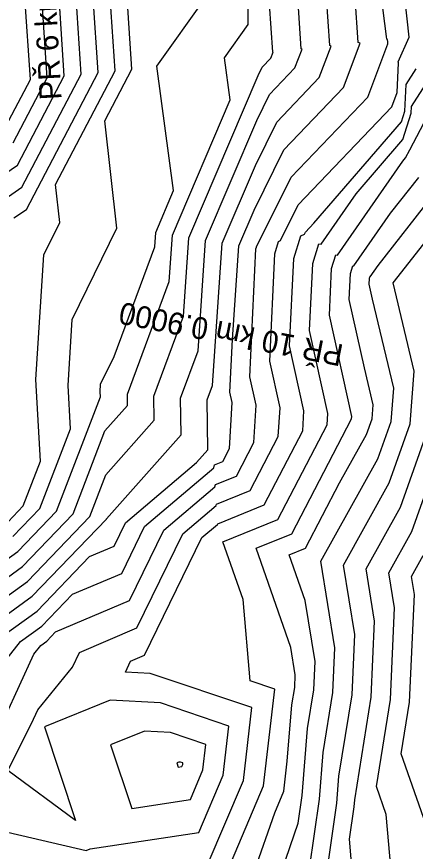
# Model space of a CAD drawing. Extents: x -549394 to -546608, y -1037055 to -1033629.
# Drawn here: x -547088.8 to -546924.3, y -1036607.7 to -1036262.8 of the extents above; entities that cross this region are included whole.
import ezdxf

# ---------------------------------------------------------------- set-up
doc = ezdxf.new("R2010")
doc.units = 0
for name, color, linetype in [('hlavni_vrst', 7, 'Continuous'), ('norm_vrst', 7, 'Continuous'), ('x_popis_pricne_rezy_C31', 7, 'Continuous')]:
    doc.layers.add(name, color=color, linetype=linetype)

msp = doc.modelspace()

# ---------------------------------------------------------------- linework, layer by layer
at = {"layer": 'hlavni_vrst'}
for p, q in [((-547069.17, -1036287.31), (-547074.04, -1036213.03)), ((-546947.86, -1036273.47), (-546950.44, -1036236.45)), ((-547030.9, -1036283.3), (-547001.91, -1036242.41)), ((-546953.97, -1036292.02), (-546947.07, -1036273.75)), ((-546947.07, -1036273.75), (-546947.86, -1036273.47)), ((-547024.04, -1036334.63), (-547030.9, -1036283.3)), ((-547088.4, -1036324.11), (-547069.17, -1036287.31)), ((-546978.56, -1036317.77), (-546953.97, -1036292.02)), ((-546926.63, -1036317.77), (-546914.41, -1036294.48)), ((-546990.87, -1036342.79), (-546978.56, -1036317.77)), ((-546928.35, -1036321.11), (-546926.63, -1036317.77)), ((-546956.43, -1036361.31), (-546929.51, -1036322.58)), ((-546929.51, -1036322.58), (-546928.35, -1036321.11)), ((-547116.55, -1036343.3), (-547088.4, -1036324.11)), ((-547031.42, -1036351.98), (-547024.04, -1036334.63)), ((-546997.11, -1036357.45), (-546990.87, -1036342.79)), ((-547031.83, -1036357.93), (-547031.42, -1036351.98)), ((-547048.58, -1036403.23), (-547031.83, -1036357.93)), ((-546999.77, -1036396.25), (-546997.11, -1036357.45)), ((-546958.86, -1036366.9), (-546957.09, -1036361.22)), ((-546957.09, -1036361.22), (-546956.43, -1036361.31)), ((-546959.77, -1036386.1), (-546958.86, -1036366.9)), ((-546950.54, -1036427.95), (-546959.77, -1036386.1)), ((-547000.8, -1036417.94), (-546999.77, -1036396.25)), ((-547054.16, -1036414.71), (-547048.58, -1036403.23)), ((-547054.36, -1036417.84), (-547054.16, -1036414.71)), ((-547072.34, -1036467.12), (-547054.25, -1036419.9)), ((-547054.25, -1036419.9), (-547054.36, -1036417.84)), ((-546999.87, -1036422.16), (-547000.8, -1036417.94)), ((-547001, -1036441.26), (-546999.87, -1036422.16)), ((-546975.3, -1036476.49), (-546950.6, -1036428.96)), ((-546950.6, -1036428.96), (-546950.54, -1036427.95)), ((-546925.75, -1036475.49), (-546910.78, -1036433.05)), ((-547003.8, -1036446.65), (-547001, -1036441.26)), ((-547007.17, -1036448.02), (-547003.8, -1036446.65)), ((-547036, -1036473.47), (-547007.5, -1036449.22)), ((-547007.5, -1036449.22), (-547007.17, -1036448.02)), ((-547088.34, -1036483.8), (-547072.34, -1036467.12)), ((-547045.45, -1036492.84), (-547036, -1036473.47)), ((-546990.03, -1036482.48), (-546975.3, -1036476.49)), ((-546935.28, -1036492.56), (-546925.75, -1036475.49)), ((-547115.54, -1036503.49), (-547088.34, -1036483.8)), ((-546975.7, -1036523.47), (-546990.03, -1036482.48)), ((-546932.91, -1036507.04), (-546935.28, -1036492.56)), ((-547065.71, -1036501.45), (-547045.45, -1036492.84)), ((-547078.36, -1036514.64), (-547065.71, -1036501.45)), ((-546934.61, -1036544.99), (-546932.91, -1036507.04)), ((-547087.14, -1036521), (-547078.36, -1036514.64)), ((-547097.18, -1036533.65), (-547087.14, -1036521)), ((-546973.86, -1036534.72), (-546975.7, -1036523.47)), ((-546974.09, -1036540.01), (-546973.86, -1036534.72)), ((-546975.24, -1036547.16), (-546974.09, -1036540.01)), ((-546977.14, -1036570.47), (-546975.24, -1036547.16)), ((-546940.39, -1036580.9), (-546934.61, -1036544.99)), ((-547021.85, -1036570.78), (-547022.77, -1036571.15)), ((-547022.77, -1036571.15), (-547022.2, -1036572.86)), ((-547021.15, -1036570.81), (-547021.85, -1036570.78)), ((-547020.2, -1036571.14), (-547021.15, -1036570.81)), ((-547020.62, -1036572.62), (-547020.28, -1036571.82)), ((-547020.28, -1036571.82), (-547020.2, -1036571.14)), ((-546978.57, -1036582.85), (-546977.14, -1036570.47)), ((-547022.2, -1036572.86), (-547020.62, -1036572.62)), ((-546936.34, -1036592.46), (-546940.39, -1036580.9)), ((-546982.33, -1036591.7), (-546978.57, -1036582.85)), ((-546994.44, -1036626.7), (-546982.33, -1036591.7)), ((-546934.27, -1036616.63), (-546936.34, -1036592.46))]:
    msp.add_line(p, q, dxfattribs=at)
at = {"layer": 'norm_vrst'}
for p, q in [((-547055.19, -1036285.88), (-547062.02, -1036181.85)), ((-546993.29, -1036266.03), (-546992.9, -1036187.88)), ((-547062.18, -1036286.6), (-547068.37, -1036192.34)), ((-546936.18, -1036271.07), (-546946.39, -1036192.56)), ((-546959.62, -1036274.79), (-546964.71, -1036201.82)), ((-546971.37, -1036276.11), (-546975.56, -1036216.01)), ((-547048.21, -1036285.17), (-547052.63, -1036217.76)), ((-547076.15, -1036288.03), (-547079.72, -1036233.71)), ((-546926.84, -1036271.25), (-546929.11, -1036250.4)), ((-547083.14, -1036288.74), (-547085.4, -1036254.39)), ((-547041.22, -1036284.45), (-547043.24, -1036253.68)), ((-546983.13, -1036277.42), (-546984.51, -1036257.66)), ((-547003.08, -1036279.84), (-546993.29, -1036266.03)), ((-546936.1, -1036272.15), (-546936.18, -1036271.07)), ((-546931.41, -1036281.41), (-546926.84, -1036271.25)), ((-546963.97, -1036288.02), (-546959.05, -1036274.99)), ((-546959.05, -1036274.99), (-546959.62, -1036274.79)), ((-546943.96, -1036296.01), (-546935.65, -1036274.01)), ((-546935.8, -1036272.26), (-546936.1, -1036272.15)), ((-546935.62, -1036273.21), (-546935.8, -1036272.26)), ((-546935.65, -1036274.01), (-546935.62, -1036273.21)), ((-546983.99, -1036280.03), (-546983.02, -1036277.46)), ((-546983.02, -1036277.46), (-546983.13, -1036277.42)), ((-546973.98, -1036284.02), (-546971.03, -1036276.23)), ((-546971.03, -1036276.23), (-546971.37, -1036276.11)), ((-547000.76, -1036297.17), (-547003.08, -1036279.84)), ((-546987.44, -1036283.64), (-546983.99, -1036280.03)), ((-546931.75, -1036294.19), (-546931.32, -1036281.88)), ((-546931.32, -1036281.88), (-546931.41, -1036281.41)), ((-546925.95, -1036300), (-546913.32, -1036280.25)), ((-547072.77, -1036332.15), (-547048.21, -1036285.17)), ((-547052.43, -1036305.9), (-547041.22, -1036284.45)), ((-546989.17, -1036287.16), (-546987.44, -1036283.64)), ((-546984.48, -1036295.02), (-546973.98, -1036284.02)), ((-546928.07, -1036290.8), (-546923.97, -1036284.4)), ((-547092.04, -1036305.75), (-547083.14, -1036288.74)), ((-547090.22, -1036314.93), (-547076.15, -1036288.03)), ((-547086.58, -1036333.28), (-547062.18, -1036286.6)), ((-547084.77, -1036342.46), (-547055.19, -1036285.88)), ((-547017.7, -1036354.17), (-546989.17, -1036287.16)), ((-546981.52, -1036306.39), (-546963.97, -1036288.02)), ((-546928.69, -1036301.91), (-546928.07, -1036290.8)), ((-546989.74, -1036305.7), (-546984.48, -1036295.02)), ((-546975.61, -1036329.14), (-546943.96, -1036296.01)), ((-546933.95, -1036300.01), (-546931.75, -1036294.19)), ((-547024.56, -1036353.08), (-547000.76, -1036297.17)), ((-546972.65, -1036340.51), (-546933.95, -1036300.01)), ((-546930, -1036306.2), (-546928.69, -1036301.91)), ((-546929.44, -1036313.62), (-546926.09, -1036302.63)), ((-546926.09, -1036302.63), (-546925.95, -1036300)), ((-547047.46, -1036350.21), (-547052.43, -1036305.9)), ((-547010.84, -1036355.26), (-546989.74, -1036305.7)), ((-546966.15, -1036348.19), (-546930, -1036306.2)), ((-546990.3, -1036324.25), (-546981.52, -1036306.39)), ((-546948.68, -1036335.95), (-546929.44, -1036313.62)), ((-547003.98, -1036356.36), (-546990.3, -1036324.25)), ((-546989.78, -1036357.95), (-546975.61, -1036329.14)), ((-546934.57, -1036344.07), (-546922.91, -1036329.21)), ((-547103.24, -1036344.64), (-547086.58, -1036333.28)), ((-547071, -1036347.87), (-547072.77, -1036332.15)), ((-546963.17, -1036356.8), (-546948.68, -1036335.95)), ((-546939.64, -1036365.56), (-546917.47, -1036337.31)), ((-546979.94, -1036355.34), (-546972.65, -1036340.51)), ((-547089.94, -1036345.99), (-547084.77, -1036342.46)), ((-546949.69, -1036365.81), (-546934.57, -1036344.07)), ((-546933.49, -1036372.76), (-546912.03, -1036345.41)), ((-547077.52, -1036361.28), (-547071, -1036347.87)), ((-547065.84, -1036387.99), (-547047.46, -1036350.21)), ((-546969.69, -1036351.89), (-546966.15, -1036348.19)), ((-547025.88, -1036372.25), (-547024.56, -1036353.08)), ((-547019.92, -1036386.57), (-547017.7, -1036354.17)), ((-546974.48, -1036362.8), (-546971.55, -1036353.43)), ((-546971.55, -1036353.43), (-546970.1, -1036352.73)), ((-546970.1, -1036352.73), (-546969.69, -1036351.89)), ((-547013.97, -1036400.89), (-547010.84, -1036355.26)), ((-547008.01, -1036415.21), (-547003.98, -1036356.36)), ((-546990.1, -1036358.7), (-546989.88, -1036358)), ((-546989.88, -1036358), (-546989.78, -1036357.95)), ((-546982.29, -1036360.75), (-546980.72, -1036355.72)), ((-546980.72, -1036355.72), (-546979.94, -1036355.34)), ((-546966.67, -1036364.85), (-546964.12, -1036356.68)), ((-546964.12, -1036356.68), (-546963.17, -1036356.8)), ((-547080.81, -1036412.66), (-547077.52, -1036361.28)), ((-546992.59, -1036411.57), (-546990.1, -1036358.7)), ((-546984.38, -1036405.21), (-546982.29, -1036360.75)), ((-546976.18, -1036398.84), (-546974.48, -1036362.8)), ((-546967.97, -1036392.47), (-546966.67, -1036364.85)), ((-546951.06, -1036368.95), (-546950.06, -1036365.77)), ((-546950.06, -1036365.77), (-546949.69, -1036365.81)), ((-546942.95, -1036370.32), (-546939.64, -1036365.56)), ((-546951.56, -1036379.73), (-546951.06, -1036368.95)), ((-546943.36, -1036373.36), (-546943.25, -1036371.01)), ((-546943.25, -1036371.01), (-546943.03, -1036370.31)), ((-546943.03, -1036370.31), (-546942.95, -1036370.32)), ((-547043.1, -1036418.85), (-547025.88, -1036372.25)), ((-546942, -1036379.52), (-546943.36, -1036373.36)), ((-546924.78, -1036409.25), (-546933.49, -1036372.76)), ((-546945.36, -1036407.86), (-546951.56, -1036379.73)), ((-546933.24, -1036416.24), (-546942, -1036379.52)), ((-547067.58, -1036415.25), (-547065.84, -1036387.99)), ((-547032.14, -1036419.62), (-547019.92, -1036386.57)), ((-546960.41, -1036426.79), (-546967.97, -1036392.47)), ((-546970.27, -1036425.63), (-546976.18, -1036398.84)), ((-547021.18, -1036420.4), (-547013.97, -1036400.89)), ((-546980.14, -1036424.47), (-546984.38, -1036405.21)), ((-546941.69, -1036423.24), (-546945.36, -1036407.86)), ((-546926.46, -1036431.02), (-546924.78, -1036409.25)), ((-547078.97, -1036446.41), (-547080.81, -1036412.66)), ((-546990, -1036423.32), (-546992.59, -1036411.57)), ((-547066.61, -1036433.16), (-547067.58, -1036415.25)), ((-547010.21, -1036421.17), (-547008.01, -1036415.21)), ((-546934.3, -1036430.01), (-546933.24, -1036416.24)), ((-547043.04, -1036423.48), (-547043.1, -1036418.85)), ((-547032, -1036429.56), (-547032.14, -1036419.62)), ((-547052.36, -1036433.96), (-547043.04, -1036423.48)), ((-547020.96, -1036435.65), (-547021.18, -1036420.4)), ((-547009.92, -1036441.73), (-547010.21, -1036421.17)), ((-546990.92, -1036438.8), (-546990, -1036423.32)), ((-546942.14, -1036429), (-546941.69, -1036423.24)), ((-546980.84, -1036436.34), (-546980.14, -1036424.47)), ((-546970.76, -1036433.88), (-546970.27, -1036425.63)), ((-546960.68, -1036431.42), (-546960.41, -1036426.79)), ((-547052.03, -1036452.1), (-547032, -1036429.56)), ((-546944.42, -1036435.47), (-546942.14, -1036429)), ((-546939.75, -1036445.48), (-546934.3, -1036430.01)), ((-547079.2, -1036466.02), (-547066.61, -1036433.16)), ((-546986.7, -1036464.55), (-546970.76, -1036433.88)), ((-546981, -1036470.52), (-546960.68, -1036431.42)), ((-546935.09, -1036455.48), (-546926.46, -1036431.02)), ((-546930.42, -1036465.49), (-546918.62, -1036432.04)), ((-547065.49, -1036468.22), (-547052.36, -1036433.96)), ((-547051.7, -1036470.24), (-547020.96, -1036435.65)), ((-546992.4, -1036458.59), (-546980.84, -1036436.34)), ((-546955.56, -1036455.45), (-546944.42, -1036435.47)), ((-546998.1, -1036452.62), (-546990.92, -1036438.8)), ((-547014.66, -1036447.07), (-547009.92, -1036441.73)), ((-547086.06, -1036464.92), (-547078.97, -1036446.41)), ((-547043.89, -1036471.94), (-547014.66, -1036447.07)), ((-546963.35, -1036487.77), (-546939.75, -1036445.48)), ((-547058.63, -1036469.31), (-547052.03, -1036452.1)), ((-547006.73, -1036456.13), (-546998.1, -1036452.62)), ((-547028.11, -1036475), (-547006.98, -1036457.02)), ((-547006.98, -1036457.02), (-547006.73, -1036456.13)), ((-546969.6, -1036482.46), (-546955.56, -1036455.45)), ((-546953.99, -1036489.37), (-546935.09, -1036455.48)), ((-547006.29, -1036464.24), (-546992.4, -1036458.59)), ((-547092.33, -1036471.47), (-547086.06, -1036464.92)), ((-547020.22, -1036476.53), (-547006.45, -1036464.82)), ((-547006.45, -1036464.82), (-547006.29, -1036464.24)), ((-547005.85, -1036472.35), (-546986.7, -1036464.55)), ((-547090.34, -1036477.64), (-547079.2, -1036466.02)), ((-547086.34, -1036489.97), (-547065.49, -1036468.22)), ((-546944.63, -1036490.96), (-546930.42, -1036465.49)), ((-547084.35, -1036496.14), (-547058.63, -1036469.31)), ((-547082.35, -1036502.31), (-547051.77, -1036470.41)), ((-547051.77, -1036470.41), (-547051.7, -1036470.24)), ((-547003.69, -1036479.75), (-546981, -1036470.52)), ((-547048.59, -1036481.57), (-547043.89, -1036471.94)), ((-547042.3, -1036504.1), (-547028.11, -1036475)), ((-547012.33, -1036478.07), (-547005.93, -1036472.62)), ((-547005.93, -1036472.62), (-547005.85, -1036472.35)), ((-547039.16, -1036515.37), (-547020.22, -1036476.53)), ((-547036.02, -1036526.64), (-547012.33, -1036478.07)), ((-547058.67, -1036485.86), (-547048.59, -1036481.57)), ((-546995.32, -1036503.69), (-547003.69, -1036479.75)), ((-546976.36, -1036485.21), (-546969.6, -1036482.46)), ((-546969.78, -1036504.04), (-546976.36, -1036485.21)), ((-546925.92, -1036494.16), (-546921.09, -1036485.5)), ((-547080.35, -1036508.48), (-547058.67, -1036485.86)), ((-546957.48, -1036523.64), (-546963.35, -1036487.77)), ((-547120.21, -1036514.49), (-547086.34, -1036489.97)), ((-546949.29, -1036518.11), (-546953.99, -1036489.37)), ((-546941.1, -1036512.57), (-546944.63, -1036490.96)), ((-546924.72, -1036501.5), (-546925.92, -1036494.16)), ((-547111.94, -1036516.12), (-547084.35, -1036496.14)), ((-547103.67, -1036517.74), (-547082.35, -1036502.31)), ((-546926.71, -1036545.99), (-546924.72, -1036501.5)), ((-547072.74, -1036517.04), (-547042.3, -1036504.1)), ((-546992.4, -1036537.24), (-546995.32, -1036503.69)), ((-546965.67, -1036529.18), (-546969.78, -1036504.04)), ((-547095.4, -1036519.37), (-547080.35, -1036508.48)), ((-546942.5, -1036543.99), (-546941.1, -1036512.57)), ((-547062.89, -1036525.46), (-547039.16, -1036515.37)), ((-547076.36, -1036520.81), (-547072.74, -1036517.04)), ((-546950.4, -1036543), (-546949.29, -1036518.11)), ((-547081.74, -1036526.24), (-547078.87, -1036522.63)), ((-547078.87, -1036522.63), (-547076.36, -1036520.81)), ((-547093.46, -1036552.08), (-547081.74, -1036526.24)), ((-547065.75, -1036531.62), (-547062.89, -1036525.46)), ((-547041.77, -1036529.08), (-547036.02, -1036526.64)), ((-546958.3, -1036542), (-546957.48, -1036523.64)), ((-547043.86, -1036533.58), (-547041.77, -1036529.08)), ((-546966.2, -1036541), (-546965.67, -1036529.18)), ((-547080.07, -1036549.19), (-547065.75, -1036531.62)), ((-547043.86, -1036533.58), (-547043.85, -1036533.6)), ((-547033.67, -1036534.15), (-547043.85, -1036533.6)), ((-546991.77, -1036548.27), (-547033.67, -1036534.15)), ((-546982.29, -1036540.65), (-546992.4, -1036537.24)), ((-546986.91, -1036580.65), (-546982.29, -1036540.65)), ((-546968.77, -1036556.98), (-546966.2, -1036541)), ((-546962.29, -1036566.81), (-546958.3, -1036542)), ((-546955.82, -1036576.63), (-546950.4, -1036543)), ((-546949.34, -1036586.46), (-546942.5, -1036543.99)), ((-547050.17, -1036545.26), (-547077.3, -1036556.27)), ((-547029.5, -1036546.37), (-547050.17, -1036545.26)), ((-547001.24, -1036555.89), (-547029.5, -1036546.37)), ((-546930.16, -1036567.42), (-546926.71, -1036545.99)), ((-547082.64, -1036554.84), (-547080.07, -1036549.19)), ((-546995.25, -1036578.44), (-546991.77, -1036548.27)), ((-547092.42, -1036574.24), (-547082.64, -1036554.84)), ((-547077.3, -1036556.27), (-547064.45, -1036594.95)), ((-547036.01, -1036558.02), (-547050.04, -1036563.71)), ((-547025.33, -1036558.59), (-547036.01, -1036558.02)), ((-547003.59, -1036576.23), (-547001.24, -1036555.89)), ((-546971.01, -1036584.62), (-546968.77, -1036556.98)), ((-547010.72, -1036563.51), (-547025.33, -1036558.59)), ((-547050.04, -1036563.71), (-547041.33, -1036589.92)), ((-547011.93, -1036574.03), (-547010.72, -1036563.51)), ((-546963.87, -1036586.17), (-546962.29, -1036566.81)), ((-546919.98, -1036596.49), (-546930.16, -1036567.42)), ((-547064.45, -1036594.95), (-547092.42, -1036574.24)), ((-547017.13, -1036586.25), (-547011.93, -1036574.03)), ((-547013.64, -1036599.87), (-547003.59, -1036576.23)), ((-547010.16, -1036613.49), (-546995.25, -1036578.44)), ((-546956.72, -1036587.72), (-546955.82, -1036576.63)), ((-547001.73, -1036615.51), (-546986.91, -1036580.65)), ((-546972.65, -1036595.99), (-546971.01, -1036584.62)), ((-547041.33, -1036589.92), (-547017.13, -1036586.25)), ((-546967.98, -1036614.76), (-546963.87, -1036586.17)), ((-546963.31, -1036633.53), (-546956.72, -1036587.72)), ((-546949.57, -1036589.27), (-546949.34, -1036586.46)), ((-546951.49, -1036602.61), (-546949.57, -1036589.27)), ((-546984.28, -1036629.61), (-546972.65, -1036595.99)), ((-547100.6, -1036597.93), (-547060.05, -1036607.35)), ((-547058.49, -1036606.68), (-547013.64, -1036599.87)), ((-546949.42, -1036626.82), (-546951.49, -1036602.61)), ((-547060.05, -1036607.35), (-547058.49, -1036606.68))]:
    msp.add_line(p, q, dxfattribs=at)

# ---------------------------------------------------------------- texts
at = {"layer": 'x_popis_pricne_rezy_C31'}
for s, rotation, p in [('PŘ 6 km 0.5000', 93.2502, (-547070.2, -1036297)), ('PŘ 10 km 0.9000', 169.0282, (-546953.53, -1036398.45))]:
    msp.add_text(s, height=9.0627, rotation=rotation, dxfattribs=at).set_placement(p)

doc.saveas('drawing.dxf')
